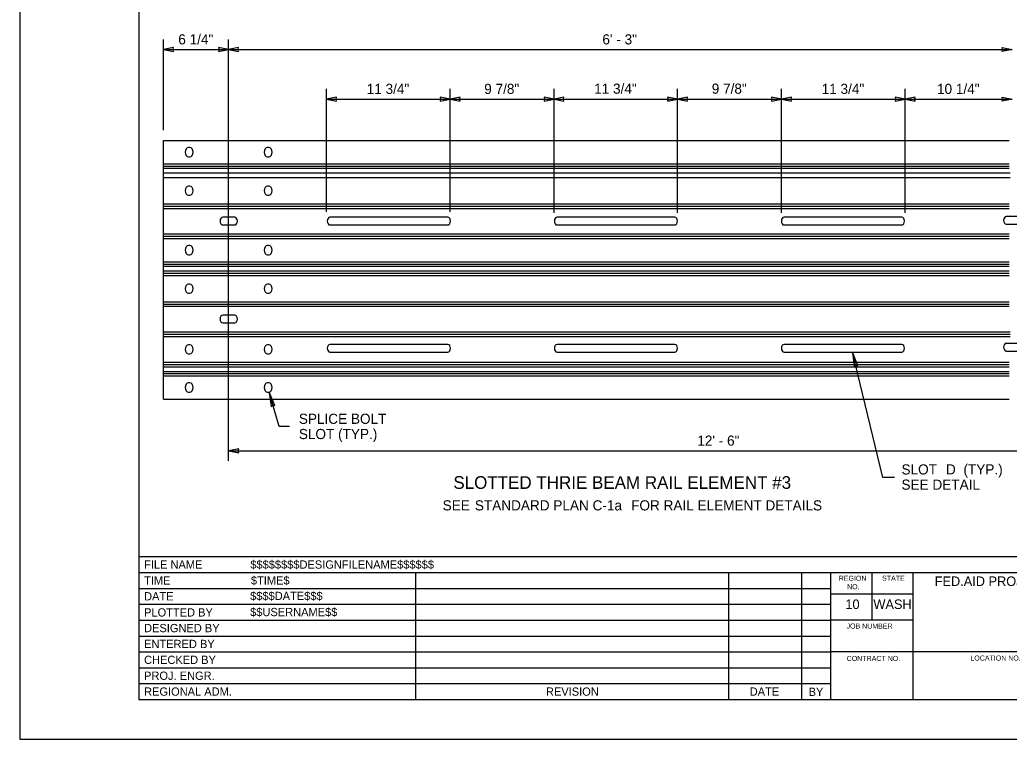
# Model space of a CAD drawing. Extents: x 1312564.2 to 1312581.5, y 1207298.4 to 1207352.6.
# Drawn here: x 1312564.48 to 1312572.27, y 1207341.62 to 1207347.29 of the extents above; entities that cross this region are included whole.
import ezdxf

# ---------------------------------------------------------------- set-up
doc = ezdxf.new("R2010")
doc.units = 0
for name, color, linetype in [('Level 1', 7, 'Continuous'), ('Level 14', 7, 'Continuous'), ('Level 15', 7, 'Continuous'), ('Level 2', 7, 'Continuous'), ('Level 20', 7, 'Continuous'), ('Level 36', 7, 'Continuous'), ('Level 6', 7, 'Continuous'), ('Level 8', 7, 'Continuous'), ('SH_GI_SheetTextInCells', 7, 'Continuous')]:
    doc.layers.add(name, color=color, linetype=linetype)

msp = doc.modelspace()

# ---------------------------------------------------------------- linework, layer by layer
at = {"layer": 'Level 1'}
for p, q in [((1312565.4155, 1207352.3083), (1312565.4155, 1207341.9333)), ((1312565.4155, 1207343.0592), (1312581.1655, 1207343.0592)), ((1312565.4155, 1207342.9341), (1312572.8721, 1207342.9341)), ((1312567.5945, 1207342.9341), (1312567.5945, 1207341.9333)), ((1312570.0565, 1207342.9341), (1312570.0565, 1207341.9333)), ((1312570.6319, 1207342.9341), (1312570.6319, 1207341.9333)), ((1312570.8605, 1207342.9341), (1312570.8605, 1207341.9333)), ((1312571.1874, 1207342.5588), (1312571.1874, 1207342.9341)), ((1312571.511, 1207341.9333), (1312571.511, 1207342.9341)), ((1312565.4155, 1207342.809), (1312567.5976, 1207342.809)), ((1312567.5976, 1207342.809), (1312570.8621, 1207342.809)), ((1312571.5112, 1207342.7643), (1312570.8621, 1207342.7643)), ((1312565.4155, 1207342.6839), (1312567.5976, 1207342.6839)), ((1312567.5976, 1207342.6839), (1312570.8621, 1207342.6839)), ((1312565.4155, 1207342.5588), (1312570.8621, 1207342.5588)), ((1312571.5112, 1207342.5588), (1312570.8621, 1207342.5588)), ((1312565.4155, 1207342.4337), (1312570.8621, 1207342.4337)), ((1312565.4155, 1207342.3086), (1312570.8621, 1207342.3086)), ((1312572.8721, 1207342.3086), (1312570.8621, 1207342.3086)), ((1312565.4155, 1207342.1835), (1312570.8621, 1207342.1835)), ((1312565.4155, 1207342.0584), (1312570.8621, 1207342.0584)), ((1312565.4155, 1207341.9333), (1312581.1655, 1207341.9333))]:
    msp.add_line(p, q, dxfattribs=at)
at = {"layer": 'Level 14'}
msp.add_lwpolyline([(1312571.3653, 1207343.6824), (1312571.2713, 1207343.6824), (1312571.0345, 1207344.67)], dxfattribs=at)
msp.add_lwpolyline([(1312571.0345, 1207344.67), (1312571.0466, 1207344.5556), (1312571.0599, 1207344.5642), (1312571.0756, 1207344.5625)], close=True, dxfattribs=at)
at = {"layer": 'Level 15'}
for p, q in [((1312565.609, 1207346.4185), (1312565.609, 1207347.133)), ((1312566.1218, 1207343.8126), (1312566.1218, 1207347.133)), ((1312565.6104, 1207347.053), (1312566.1218, 1207347.053)), ((1312566.1218, 1207347.053), (1312572.2907, 1207347.053)), ((1312566.8925, 1207345.7755), (1312566.8925, 1207346.7429)), ((1312567.8657, 1207345.7755), (1312567.8657, 1207346.7429)), ((1312568.6836, 1207345.7671), (1312568.6836, 1207346.7429)), ((1312569.6568, 1207345.7671), (1312569.6568, 1207346.7429)), ((1312570.4747, 1207345.7671), (1312570.4747, 1207346.7429)), ((1312571.4479, 1207345.7671), (1312571.4479, 1207346.7429)), ((1312566.1228, 1207343.8926), (1312573.8441, 1207343.8926))]:
    msp.add_line(p, q, dxfattribs=at)
for points in [[(1312572.2907, 1207347.053), (1312572.2121, 1207347.0376), (1312572.2157, 1207347.053), (1312572.2121, 1207347.0684)], [(1312566.1228, 1207343.8926), (1312566.2014, 1207343.8772), (1312566.1977, 1207343.8926), (1312566.2014, 1207343.908)]]:
    msp.add_lwpolyline(points, close=True, dxfattribs=at)
at = {"layer": 'Level 2'}
msp.add_lwpolyline([(1312564.478, 1207341.6208), (1312581.478, 1207341.6208), (1312581.478, 1207352.6208), (1312564.478, 1207352.6208)], close=True, dxfattribs=at)
at = {"layer": 'Level 6'}
for p, q in [((1312566.8925, 1207346.6629), (1312567.8657, 1207346.6629)), ((1312567.8657, 1207346.6629), (1312568.6836, 1207346.6629)), ((1312568.6836, 1207346.6629), (1312569.6568, 1207346.6629)), ((1312569.6568, 1207346.6629), (1312570.4747, 1207346.6629)), ((1312570.4747, 1207346.6629), (1312571.4479, 1207346.6629)), ((1312571.4479, 1207346.6629), (1312572.2907, 1207346.6629)), ((1312565.8177, 1207346.2812), (1312565.8051, 1207346.2812)), ((1312566.44, 1207346.2812), (1312566.4274, 1207346.2812)), ((1312565.61, 1207346.1524), (1312572.2662, 1207346.1524)), ((1312565.8051, 1207346.2086), (1312565.8177, 1207346.2086)), ((1312566.4274, 1207346.2086), (1312566.44, 1207346.2086)), ((1312565.61, 1207346.1349), (1312572.2662, 1207346.1349)), ((1312565.61, 1207346.1174), (1312572.2662, 1207346.1174)), ((1312565.61, 1207346.0811), (1312572.2741, 1207346.0811)), ((1312565.61, 1207346.0461), (1312572.2741, 1207346.0461)), ((1312565.8177, 1207345.9778), (1312565.8051, 1207345.9778)), ((1312566.44, 1207345.9778), (1312566.4274, 1207345.9778)), ((1312565.61, 1207345.837), (1312572.2662, 1207345.837)), ((1312565.8051, 1207345.9053), (1312565.8177, 1207345.9053)), ((1312566.4274, 1207345.9053), (1312566.44, 1207345.9053)), ((1312565.61, 1207345.8195), (1312572.2662, 1207345.8195)), ((1312565.61, 1207345.8019), (1312572.2662, 1207345.8019)), ((1312566.1702, 1207345.7313), (1312566.0758, 1207345.7313)), ((1312567.8475, 1207345.7313), (1312566.9202, 1207345.7313)), ((1312569.6347, 1207345.7313), (1312568.7074, 1207345.7313)), ((1312571.4219, 1207345.7313), (1312570.4946, 1207345.7313)), ((1312572.3384, 1207345.7368), (1312572.244, 1207345.7368)), ((1312565.61, 1207345.6001), (1312572.2662, 1207345.6001)), ((1312566.0758, 1207345.6709), (1312566.1702, 1207345.6709)), ((1312566.9202, 1207345.6709), (1312567.8475, 1207345.6709)), ((1312568.7074, 1207345.6709), (1312569.6347, 1207345.6709)), ((1312570.4946, 1207345.6709), (1312571.4219, 1207345.6709)), ((1312572.244, 1207345.6764), (1312572.3384, 1207345.6764)), ((1312565.61, 1207345.5826), (1312572.2662, 1207345.5826)), ((1312565.61, 1207345.5651), (1312572.2662, 1207345.5651)), ((1312565.8177, 1207345.5089), (1312565.8051, 1207345.5089)), ((1312566.44, 1207345.5089), (1312566.4274, 1207345.5089)), ((1312565.61, 1207345.3808), (1312572.2662, 1207345.3808)), ((1312565.8051, 1207345.4364), (1312565.8177, 1207345.4364)), ((1312566.4274, 1207345.4364), (1312566.44, 1207345.4364)), ((1312565.61, 1207345.3633), (1312572.2662, 1207345.3633)), ((1312565.61, 1207345.3464), (1312572.2662, 1207345.3464)), ((1312565.61, 1207345.309), (1312570.9202, 1207345.309)), ((1312565.61, 1207345.2914), (1312572.2662, 1207345.2914)), ((1312570.9202, 1207345.309), (1312572.2662, 1207345.309)), ((1312565.61, 1207345.2739), (1312572.2662, 1207345.2739)), ((1312565.8177, 1207345.2056), (1312565.8051, 1207345.2056)), ((1312565.8051, 1207345.1331), (1312565.8177, 1207345.1331)), ((1312566.44, 1207345.2056), (1312566.4274, 1207345.2056)), ((1312566.4274, 1207345.1331), (1312566.44, 1207345.1331)), ((1312565.61, 1207345.0654), (1312572.2662, 1207345.0654)), ((1312565.61, 1207345.048), (1312572.2662, 1207345.048)), ((1312565.61, 1207345.031), (1312572.2662, 1207345.031)), ((1312566.1702, 1207344.9603), (1312566.0758, 1207344.9603)), ((1312566.0758, 1207344.8998), (1312566.1702, 1207344.8998)), ((1312565.61, 1207344.8292), (1312572.2741, 1207344.8292)), ((1312565.61, 1207344.8292), (1312572.2741, 1207344.8292)), ((1312565.61, 1207344.8111), (1312572.2741, 1207344.8111)), ((1312565.61, 1207344.7936), (1312572.2741, 1207344.7936)), ((1312565.8177, 1207344.7277), (1312565.8051, 1207344.7277)), ((1312566.44, 1207344.7277), (1312566.4274, 1207344.7277)), ((1312567.8475, 1207344.7302), (1312566.9202, 1207344.7302)), ((1312566.9202, 1207344.6697), (1312567.8475, 1207344.6697)), ((1312569.6347, 1207344.7302), (1312568.7074, 1207344.7302)), ((1312568.7074, 1207344.6697), (1312569.6347, 1207344.6697)), ((1312571.4219, 1207344.7302), (1312570.4946, 1207344.7302)), ((1312570.4946, 1207344.6697), (1312571.4219, 1207344.6697)), ((1312572.3384, 1207344.7388), (1312572.244, 1207344.7388)), ((1312572.244, 1207344.6783), (1312572.3384, 1207344.6783)), ((1312565.61, 1207344.5899), (1312572.2662, 1207344.5899)), ((1312565.8051, 1207344.6552), (1312565.8177, 1207344.6552)), ((1312566.4274, 1207344.6552), (1312566.44, 1207344.6552)), ((1312565.61, 1207344.5724), (1312572.2662, 1207344.5724)), ((1312565.61, 1207344.5549), (1312572.2662, 1207344.5549)), ((1312565.61, 1207344.518), (1312572.2662, 1207344.518)), ((1312565.61, 1207344.5005), (1312572.2662, 1207344.5005)), ((1312565.61, 1207344.483), (1312572.2662, 1207344.483)), ((1312565.8177, 1207344.4273), (1312565.8051, 1207344.4273)), ((1312565.8051, 1207344.3549), (1312565.8177, 1207344.3549)), ((1312566.44, 1207344.4273), (1312566.4274, 1207344.4273)), ((1312566.4274, 1207344.3549), (1312566.44, 1207344.3549))]:
    msp.add_line(p, q, dxfattribs=at)
for points in [[(1312565.6104, 1207347.053), (1312565.689, 1207347.0376), (1312565.6853, 1207347.053), (1312565.689, 1207347.0684)], [(1312566.1218, 1207347.053), (1312566.0433, 1207347.0684), (1312566.0469, 1207347.053), (1312566.0433, 1207347.0376)], [(1312566.1218, 1207347.053), (1312566.2004, 1207347.0376), (1312566.1968, 1207347.053), (1312566.2004, 1207347.0684)], [(1312566.8925, 1207346.6629), (1312566.9711, 1207346.6475), (1312566.9675, 1207346.6629), (1312566.9711, 1207346.6783)], [(1312567.8659, 1207346.6629), (1312567.7873, 1207346.6783), (1312567.7909, 1207346.6629), (1312567.7873, 1207346.6475)], [(1312567.8651, 1207346.6629), (1312567.9437, 1207346.6475), (1312567.9401, 1207346.6629), (1312567.9437, 1207346.6783)], [(1312568.6836, 1207346.6629), (1312568.605, 1207346.6783), (1312568.6087, 1207346.6629), (1312568.605, 1207346.6475)], [(1312568.6836, 1207346.6629), (1312568.7622, 1207346.6475), (1312568.7585, 1207346.6629), (1312568.7622, 1207346.6783)], [(1312569.6568, 1207346.6629), (1312569.5782, 1207346.6783), (1312569.5818, 1207346.6629), (1312569.5782, 1207346.6475)], [(1312569.6568, 1207346.6629), (1312569.7354, 1207346.6475), (1312569.7317, 1207346.6629), (1312569.7354, 1207346.6783)], [(1312570.4747, 1207346.6629), (1312570.3961, 1207346.6783), (1312570.3997, 1207346.6629), (1312570.3961, 1207346.6475)], [(1312570.4747, 1207346.6629), (1312570.5533, 1207346.6475), (1312570.5496, 1207346.6629), (1312570.5533, 1207346.6783)], [(1312571.4479, 1207346.6629), (1312571.3693, 1207346.6783), (1312571.3729, 1207346.6629), (1312571.3693, 1207346.6475)], [(1312571.4479, 1207346.6629), (1312571.5264, 1207346.6475), (1312571.5228, 1207346.6629), (1312571.5264, 1207346.6783)], [(1312572.2907, 1207346.6629), (1312572.2121, 1207346.6475), (1312572.2157, 1207346.6629), (1312572.2121, 1207346.6783)], [(1312566.4401, 1207344.355), (1312566.4582, 1207344.2414), (1312566.471, 1207344.2507), (1312566.4868, 1207344.2499)]]:
    msp.add_lwpolyline(points, close=True, dxfattribs=at)
msp.add_lwpolyline([(1312566.6023, 1207344.0846), (1312566.5204, 1207344.0846), (1312566.4401, 1207344.355)], dxfattribs=at)
for centre, major_axis in [((1312565.8052, 1207346.2447), (0, -0.0363)), ((1312565.8178, 1207346.2447), (0, 0.0363)), ((1312566.4275, 1207346.2447), (0, -0.0363)), ((1312566.4401, 1207346.2447), (0, 0.0363)), ((1312565.8052, 1207345.9417), (0, -0.0363)), ((1312565.8178, 1207345.9417), (0, 0.0363)), ((1312566.4275, 1207345.9417), (0, -0.0363)), ((1312566.4401, 1207345.9417), (0, 0.0363)), ((1312566.0757, 1207345.7012), (0, -0.0302)), ((1312566.1701, 1207345.7012), (0, 0.0302)), ((1312566.9201, 1207345.7012), (0, -0.0302)), ((1312567.8474, 1207345.7012), (0, 0.0302)), ((1312568.7073, 1207345.7012), (0, -0.0302)), ((1312569.6346, 1207345.7012), (0, 0.0302)), ((1312570.4945, 1207345.7012), (0, -0.0302)), ((1312571.4218, 1207345.7012), (0, 0.0302)), ((1312572.2439, 1207345.7068), (0, -0.0302)), ((1312565.8052, 1207345.4728), (0, -0.0363)), ((1312565.8178, 1207345.4728), (0, 0.0363)), ((1312566.4275, 1207345.4728), (0, -0.0363)), ((1312566.4401, 1207345.4728), (0, 0.0363)), ((1312565.8052, 1207345.1695), (0, -0.0363)), ((1312565.8178, 1207345.1695), (0, 0.0363)), ((1312566.4275, 1207345.1695), (0, -0.0363)), ((1312566.4401, 1207345.1695), (0, 0.0363)), ((1312566.0757, 1207344.9302), (0, -0.0302)), ((1312566.1701, 1207344.9302), (0, 0.0302)), ((1312565.8052, 1207344.6916), (0, -0.0363)), ((1312565.8178, 1207344.6916), (0, 0.0363)), ((1312566.4275, 1207344.6916), (0, -0.0363)), ((1312566.4401, 1207344.6916), (0, 0.0363)), ((1312566.9201, 1207344.7001), (0, -0.0302)), ((1312567.8474, 1207344.7001), (0, 0.0302)), ((1312568.7073, 1207344.7001), (0, -0.0302)), ((1312569.6346, 1207344.7001), (0, 0.0302)), ((1312570.4945, 1207344.7001), (0, -0.0302)), ((1312571.4218, 1207344.7001), (0, 0.0302)), ((1312572.2439, 1207344.7087), (0, -0.0302)), ((1312565.8052, 1207344.3913), (0, -0.0363)), ((1312565.8178, 1207344.3913), (0, 0.0363)), ((1312566.4275, 1207344.3913), (0, -0.0363)), ((1312566.4401, 1207344.3913), (0, 0.0363))]:
    msp.add_ellipse(centre, major_axis=major_axis, ratio=0.694444, start_param=3.141593, end_param=6.283185, dxfattribs=at)
at = {"layer": 'Level 8'}
for p, q in [((1312565.61, 1207344.2993), (1312565.61, 1207346.3367)), ((1312565.61, 1207346.3367), (1312572.2662, 1207346.3367)), ((1312565.61, 1207344.2993), (1312572.2662, 1207344.2993))]:
    msp.add_line(p, q, dxfattribs=at)

# ---------------------------------------------------------------- texts
at = {"layer": 'Level 20'}
for s, height, p in [('6 1/4"', 0.07995, (1312565.7257, 1207347.093)), ('6\' - 3"', 0.07995, (1312569.0646, 1207347.093)), ('11 3/4"', 0.07995, (1312567.2088, 1207346.7029)), ('9 7/8"', 0.07995, (1312568.1343, 1207346.7029)), ('11 3/4"', 0.07995, (1312568.9996, 1207346.7047)), ('9 7/8"', 0.07995, (1312569.9254, 1207346.7047)), ('11 3/4"', 0.07995, (1312570.7907, 1207346.7029)), ('10 1/4"', 0.07995, (1312571.6987, 1207346.7029)), ('SPLICE BOLT ', 0.079953, (1312566.6748, 1207344.1046)), ('SLOT (TYP.)', 0.079953, (1312566.6748, 1207343.9847)), ('12\' - 6"', 0.07995, (1312569.8116, 1207343.9326)), ('SLOT ', 0.07995, (1312571.4192, 1207343.7059)), ('D', 0.08, (1312571.7692, 1207343.7059)), ('  (TYP.)', 0.07995, (1312571.8476, 1207343.7059)), ('SLOTTED THRIE BEAM RAIL ELEMENT #3', 0.099942, (1312567.8914, 1207343.5927)), ('SEE DETAIL', 0.07995, (1312571.4192, 1207343.5859)), ('SEE ', 0.07995, (1312567.8071, 1207343.4228)), ('STANDARD PLAN C-1a', 0.079953, (1312568.0605, 1207343.4228)), (' FOR RAIL ELEMENT DETAILS', 0.079953, (1312569.2612, 1207343.4228))]:
    msp.add_text(s, height=height, dxfattribs=at).set_placement(p)
at = {"layer": 'Level 36'}
for s, height, p in [('$$$$$$$$DESIGNFILENAME$$$$$$', 0.065052, (1312566.2929, 1207342.9642)), ('$TIME$', 0.06505, (1312566.2975, 1207342.8392)), ('$$$$DATE$$$', 0.065052, (1312566.2914, 1207342.7169)), ('$$USERNAME$$', 0.065052, (1312566.2914, 1207342.59))]:
    msp.add_text(s, height=height, dxfattribs=at).set_placement(p)
at = {"layer": 'SH_GI_SheetTextInCells'}
for s, height, p in [('FILE NAME', 0.06505, (1312565.4565, 1207342.9642)), ('TIME', 0.06505, (1312565.4565, 1207342.8391)), ('REGION', 0.04003, (1312570.9253, 1207342.8685)), ('STATE', 0.04003, (1312571.2665, 1207342.869)), ('FED.AID PROJ.NO.', 0.07506, (1312571.6807, 1207342.8278)), ('NO.', 0.04003, (1312570.9907, 1207342.8023)), ('DATE', 0.06505, (1312565.4565, 1207342.714)), ('10', 0.07506, (1312570.9776, 1207342.6464)), ('WASH', 0.07506, (1312571.1981, 1207342.6464)), ('PLOTTED BY', 0.06505, (1312565.4565, 1207342.5871)), ('DESIGNED BY', 0.065052, (1312565.4565, 1207342.4638)), ('JOB NUMBER', 0.04003, (1312570.9867, 1207342.4921)), ('ENTERED BY', 0.06505, (1312565.4565, 1207342.3387)), ('CHECKED BY', 0.06505, (1312565.4565, 1207342.2136)), ('CONTRACT NO.', 0.040032, (1312570.988, 1207342.237)), ('LOCATION NO.', 0.040032, (1312571.962, 1207342.24)), ('PROJ. ENGR.', 0.065052, (1312565.4565, 1207342.0885)), ('REGIONAL ADM.', 0.065052, (1312565.4565, 1207341.9634)), ('REVISION', 0.06505, (1312568.6203, 1207341.9634)), ('DATE', 0.06505, (1312570.2246, 1207341.9634)), ('BY', 0.06505, (1312570.688, 1207341.9618))]:
    msp.add_text(s, height=height, dxfattribs=at).set_placement(p)

doc.saveas('drawing.dxf')
